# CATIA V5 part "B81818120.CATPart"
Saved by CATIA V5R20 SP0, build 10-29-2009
Part number: B81818120
Revision: 5
Definition: design
Nomenclature: B81818120
Source: made
Description: NOT SPECIFIED
Bounding box of the stored display mesh (mm): x -10.833 to 10.833, y -11 to 11, z 0 to 120
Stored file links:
  C:\Users\Raffaele\Desktop\3D X SITO CF\BOLEX\6-PILLAR REF 818\B81818120.CATPart
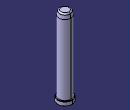
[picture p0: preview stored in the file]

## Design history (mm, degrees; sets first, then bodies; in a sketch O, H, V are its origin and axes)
Body1 "MANIFOLD_SOLID_BREP #370" (main body)
  Solid1: solid without history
